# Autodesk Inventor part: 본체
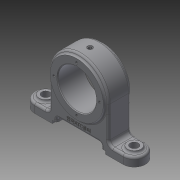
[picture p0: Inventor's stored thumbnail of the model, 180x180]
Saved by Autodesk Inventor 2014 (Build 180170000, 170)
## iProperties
Created: 2019-05
Part Number: 본체
Material: Generic
Document SubType Name: Modeling
Designer: kh
Density: 1 g/cm^3
Appearance: Default
Mass: 168.894 g
Surface Area: 318.798 cm^2
Volume: 168.894 cm^3
Author: kh
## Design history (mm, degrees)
sketch "Sketch1"
  geometry: L1 (-60, 0)-(60, 0); L2 (-60, -15)-(60, -15); L3 (60, 15)-(-60, 15); A1 r 15 centre (-60, 0) between (-60, 15) and (-60, -15); A2 r 15 centre (60, 0) between (60, -15) and (60, 15); 1 further point
  constraints: 8 end point, 4 point on circle, 4 tangent, 2 centre point, 1 horizontal, 1 midpoint, 1 parallel
  dimensions: "d0" = 150 dimension on A1 A2; "d1" = 120 distance of L1.start L1.end
extrude "Extrusion1" new body sketch "Sketch1" distance "d2" = 12; taper "d3" = 0 deg
sketch "Sketch3"
  geometry: L1 (0, 0)-(120, 0) reference; L2 (120, 0)-(120, 12) reference; L3 (0, 12)-(120, 12) reference; L4 (0, 0)-(0, 12) reference; L5 (24, 0)-(24, 4); L6 (24, 4)-(30, 4); L7 (30, 4)-(30, 10); L8 (30, 10)-(90, 10); L9 (90, 10)-(90, 4); L10 (90, 4)-(96, 4); L11 (96, 4)-(96, 0); L12 (60, 0)-(60, 12); L13 (96, 0)-(24, 0)
  constraints: 18 end point, 4 parallel, 3 perpendicular, 2 point on line, 1 collinear, 3 other
  dimensions: "d8" = 72 distance between parallel lines of L5 L11; "d9" = 60 distance between parallel lines of L7 L9; "d10" = 4 distance of L5.start L5.end; "d11" = 10 distance between parallel lines of L1 L8
extrude "Extrusion3" cut sketch "Sketch3" stored distance "d12" = 36; taper "d13" = 0 deg
sketch "Sketch5"
  geometry: C1 r 9 at (60, 0); C2 r 9 at (-60, 0); A1 r 15 centre (60, 0) between (60, -15) and (60, 15) reference; A2 r 15 centre (-60, 0) between (-60, 15) and (-60, -15) reference; 1 further point
  constraints: 2 centre point, 2 coincident
  dimensions: "d14" = 18 diameter of C1; "d15" = 18 diameter of C2
extrude "Extrusion4" join sketch "Sketch5" distance "d16" = 3; taper "d17" = 0 deg
hole "Hole1" diameter "d20" = 11; stored, may be unused: countersink angle "d24" = 90 deg, drill point angle "d26" = 118 deg; dims "d18" = 10, "d19" = 10, "d21" = 6, "d22" = 4, "d23" = 2, "d25" = 8
mirror "Mirror1"
sketch "Sketch8"
  geometry: L1 (60, 12)-(-60, 12) reference; L2 (40, 60)-(40, 12); L3 (-40, 60)-(-40, 12); L4 (40, 12)-(-40, 12); A1 r 40 centre (0, 60) between (40, 60) and (-40, 60); 1 further point
  constraints: 6 end point, 2 perpendicular, 2 point on circle, 2 point on line, 2 tangent, 1 centre point, 1 parallel, 1 vertical alignment
  dimensions: "d31" = 80 diameter of A1; "d32" = 60 distance of point (0, 0) A1.centre
extrude "Extrusion5" join sketch "Sketch8" stored distance "d33" = 30; taper "d34" = 0 deg
sketch "Sketch10"
  geometry: C1 r 36 at (-60, 60); A1 r 40 centre (-60, 60) between (-20, 60) and (-100, 60) reference; 1 further point
  constraints: 1 centre point, 1 coincident
  dimensions: "d35" = 72 diameter of C1
extrude "Extrusion6" join sketch "Sketch10" distance "d36" = 3; taper "d37" = 0 deg
mirror "Mirror2"
hole "Hole2" diameter "d40" = 52; stored, may be unused: countersink angle "d44" = 90 deg, drill point angle "d46" = 118 deg; dims "d38" = 10, "d39" = 10, "d41" = 6, "d42" = 4, "d43" = 2, "d45" = 8
fillet "Fillet1" dims "d47" = 6
sketch "Sketch11"
  geometry: L1 (0, 0)-(0, 31); C1 r 36 at (0, 0) reference; 2 further points
  constraints: 2 end point, 1 coincident, 1 vertical
  dimensions: "d49" = 31 distance of L1.start L1.end
hole "Hole3" sketch "Sketch11" at (0, 31) diameter "d50" = 3.242; stored, may be unused: countersink angle "d54" = 90 deg, drill point angle "d56" = 118 deg; dims "d51" = 6, "d52" = 4, "d53" = 2, "d55" = 8
pattern_circular "Circular Pattern1" dims angle "d58" = 360 deg
mirror "Mirror3"
workplane "Work Plane2"
sketch "Sketch12"
  geometry: L1 (35.716, 22.017)-(84.284, 22.017); L2 (84.284, 22.017)-(84.284, 11.983); L3 (84.284, 11.983)-(35.716, 11.983); L4 (35.716, 11.983)-(35.716, 22.017); L5 (35.716, 22.017)-(84.284, 11.983); L6 (30, 10)-(90, 10) reference; 2 further points
  constraints: 2 end point, 1 midpoint, 1 vertical alignment, 2 other
  dimensions: "d61" = 7 distance from line of L6 point (60, 17)
emboss "Emboss1" sketch "Sketch12" dims "d8" = 72, "d9" = 60, "d10" = 4, "d11" = 10, "d62" = 0.5, "d63" = 0
fillet "Fillet3" dims "d64" = 3
chamfer "Chamfer1" distance "d65" = 1; stored, may be unused: second distance "d66" = 2, angle "d67" = 45 deg
sketch "Sketch13"
  geometry: C1 r 1.5 at (-60, 86); 2 further points
  constraints: 2 vertical alignment, 1 centre point, 1 other
  dimensions: "d68" = 3 diameter of C1
extrude "Extrusion7" cut sketch "Sketch13" stored distance "d69" = 3; taper "d70" = 0 deg
workplane "Work Plane3"
sketch "Sketch14"
  geometry: 2 further points
  constraints: 1 coincident
hole "Hole4" sketch "Sketch14" at (0, 0) diameter "d71" = 4.917; stored, may be unused: countersink angle "d75" = 90 deg, drill point angle "d77" = 118 deg; dims "d72" = 8, "d73" = 7, "d74" = 1, "d76" = 10
workplane "Work Plane4"
sketch "Sketch15"
  geometry: C1 r 1 at (-30, 15); 1 further point
  constraints: 1 centre point, 1 coincident
  dimensions: "d79" = 2 diameter of C1
extrude "Extrusion8" cut sketch "Sketch15" stored distance "d80" = 3; taper "d81" = 0 deg
fillet "Fillet4" dims "d82" = 3
fillet "Fillet5" dims "d83" = 3
fillet "Fillet6" dims "d84" = 3
fillet "Fillet7" dims "d85" = 3
body "Solid1"
node "Projected Loop1"
other parameters: "d60" = 22.25, "d78" = -80.25
